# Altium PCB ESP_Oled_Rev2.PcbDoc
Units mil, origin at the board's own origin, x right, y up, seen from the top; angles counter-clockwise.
Board outline 1333.02 x 881.03 mil, 2 copper layers (Top Layer, Bottom Layer); 26 components, 22 nets, 116 pads, 21 vias.
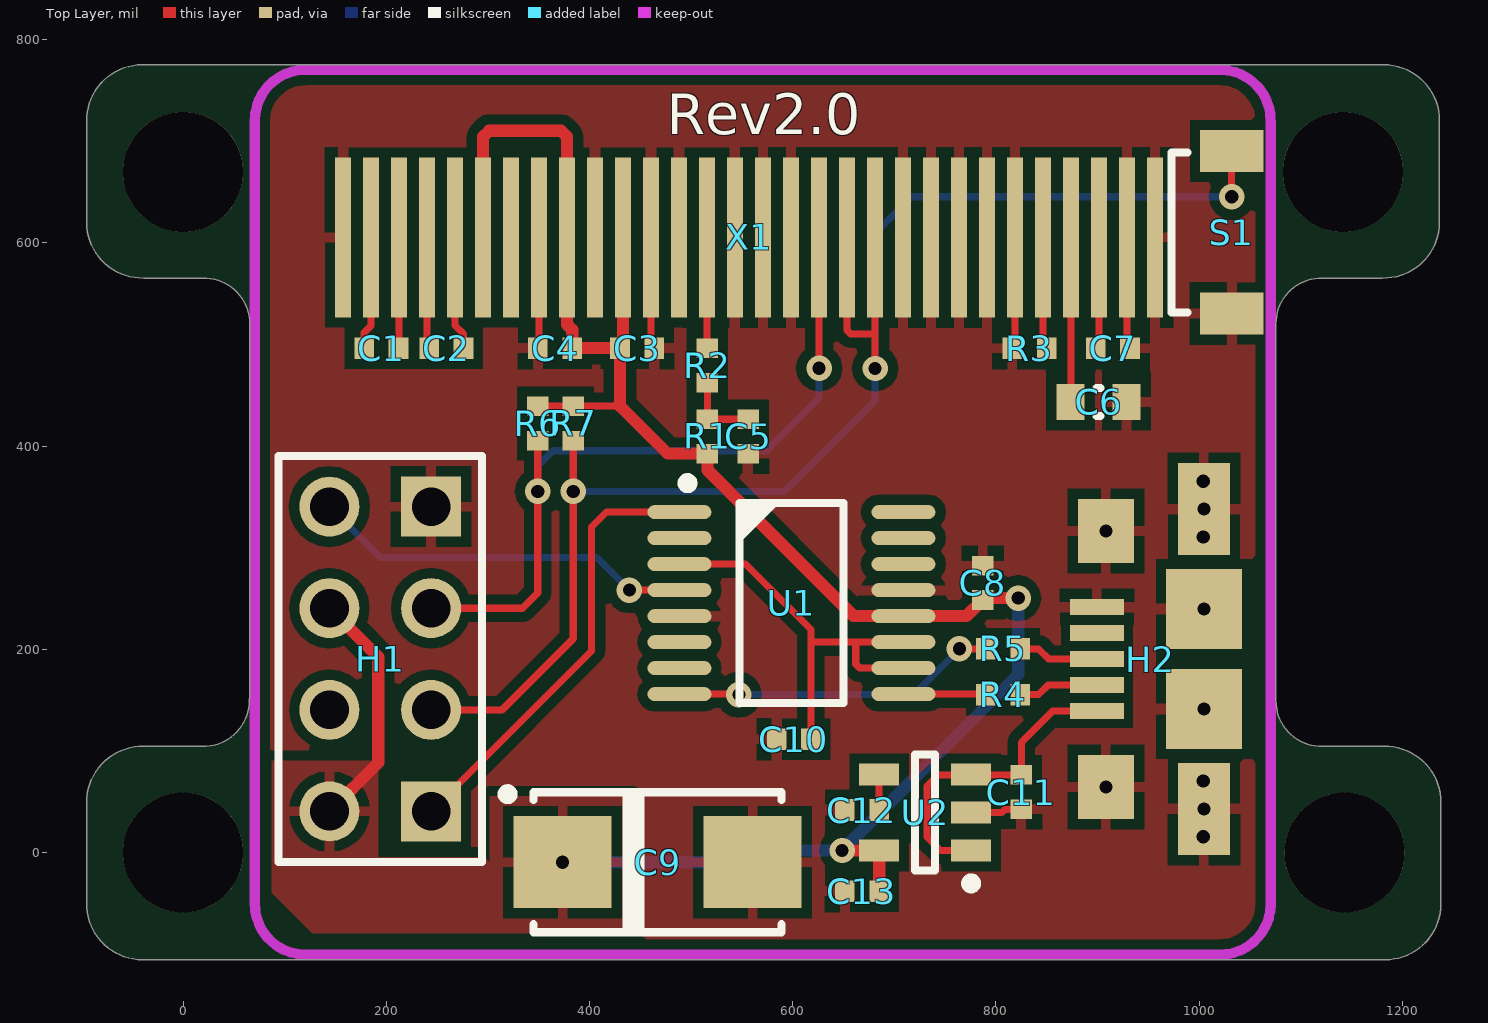
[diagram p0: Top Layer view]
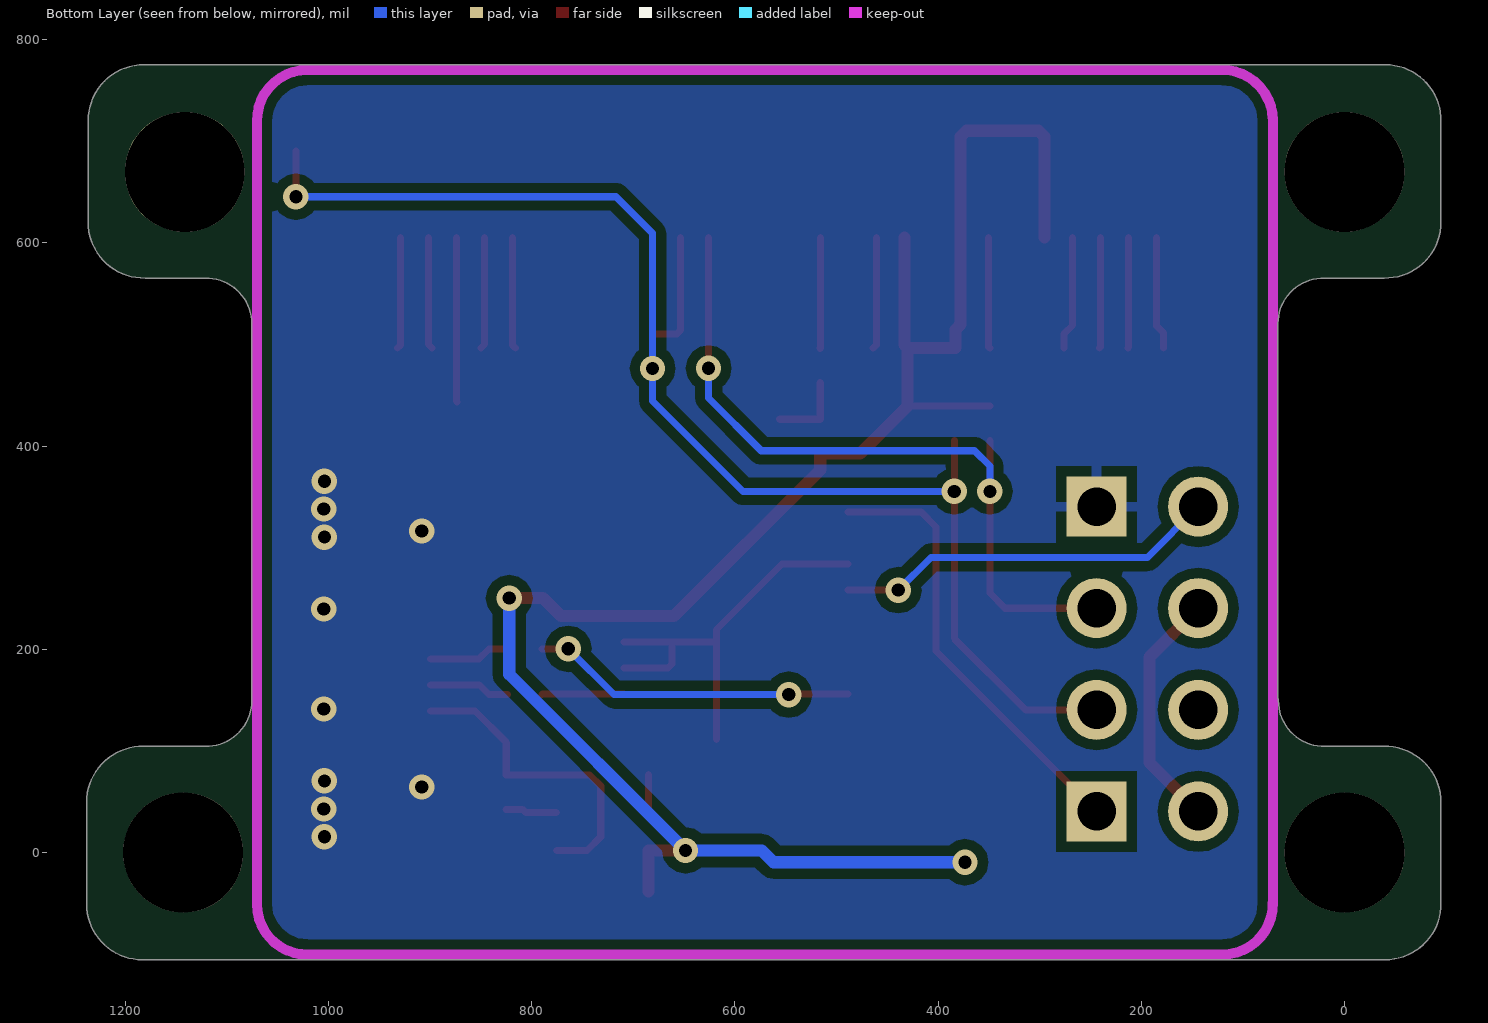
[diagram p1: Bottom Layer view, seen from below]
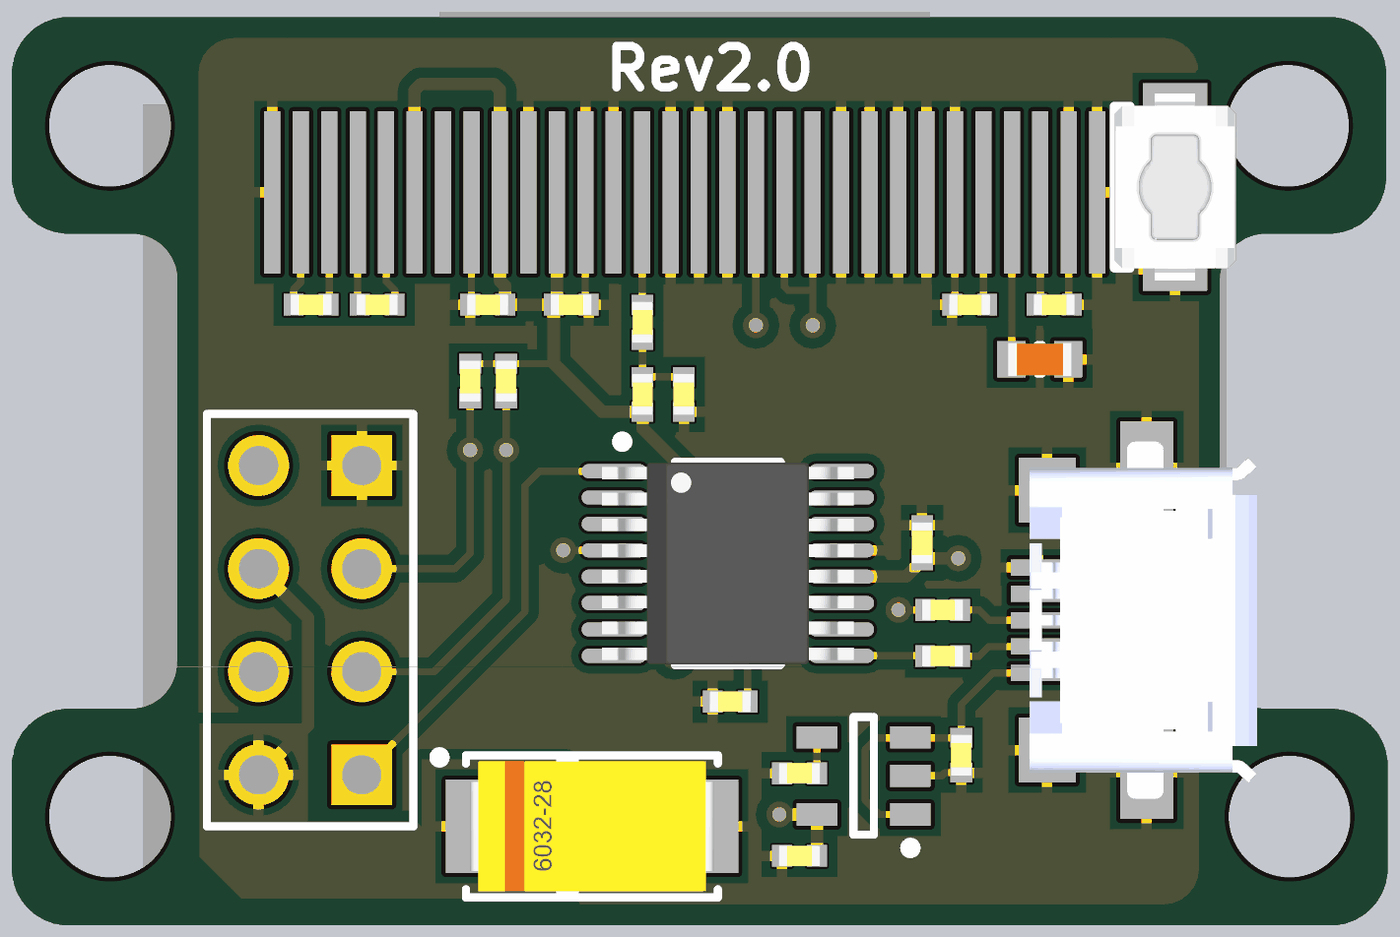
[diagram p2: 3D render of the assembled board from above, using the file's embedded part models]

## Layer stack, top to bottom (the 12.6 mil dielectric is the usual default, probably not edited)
Top Solder: solder mask 0.4, Solder Resist, Dk 3.5
Top Layer: signal copper 1.4
Dielectric 1: dielectric 12.6, FR-4, Dk 4.8
Bottom Layer: signal copper 1.4
Bottom Solder: solder mask 0.4, Solder Resist, Dk 3.5

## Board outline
-95.01,-49.43 ccw(c-40,-50.48) -40,-105.49 ccw(c-40,-100.48) -40,-105.49 120.02,-105.49 ccw(c120.5,-100.5) 120.5,-105.52 1019.5,-105.52 ccw(c1019.5,-100.5) 1020.11,-105.48 1182.56,-105.48 ccw(c1183,-100.48) 1183,-105.5 ccw(c1183,-50.48) 1238.01,-50.48 ccw(c1183,-50.48) 1238,-49.43 ccw(c1183,-50.48) 1238,-49.38 1238,-49.48 1238,49.52 ccw(c1182.99,49.52) 1181.94,104.52 ccw(c1182.99,49.52) 1181.89,104.52 1181.99,104.52 1121.5,104.52 ccw(c1121.5,99.51) 1121.37,104.52 cw(c1120.5,149.5) 1075.51,149.5 1075.51,520.5 cw(c1120.5,520.5) 1121.37,565.48 cw(c1120.5,520.5) 1121.4,565.48 1121.37,565.48 ccw(c1121.5,570.49) 1121.5,565.47 1180.44,565.47 ccw(c1181.49,620.48) 1236.5,620.48 1236.5,719.43 ccw(c1181.5,720.48) 1236.51,720.48 ccw(c1181.5,720.48) 1181.5,775.49 ccw(c1181.5,720.48) 1181.5,775.49 -40,775.52 ccw(c-40,770.5) -40.5,775.49 ccw(c-40,720.48) -95.01,719.43 ccw(c-40,720.48) -95,719.38 -95.01,719.48 -95.01,620.48 ccw(c-39.99,620.48) -38.94,565.47 ccw(c-39.99,620.48) -38.89,565.48 -38.99,565.47 19.5,565.47 ccw(c19.5,570.49) 19.63,565.48 ccw(c20.5,520.5) 19.6,565.48 19.63,565.48 cw(c20.5,520.5) 65.48,520.5 65.48,152.5 ccw(c70.5,152.5) 65.54,151.79 ccw(c70,149.5) 64.98,149.5 cw(c20,149.5) 19.15,104.52 cw(c20,149.5) 19.1,104.52 19.15,104.52 ccw(c19,99.51) 19,104.53 -38.94,104.53 cw(c-39.99,49.52) -38.89,104.52 -38.94,104.53 ccw(c-39.99,49.52) -95.01,49.52 -95.01,-49.43 cw(c-40,-50.48)

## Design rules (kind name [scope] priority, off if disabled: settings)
Clearance Clearance_H2 [InComponent('H2')] p1: gap=9
Clearance [All] p2: gap=10
MinimumSolderMaskSliver [All] p1: minsoldermaskwidth=3
PolygonConnect PolygonConnect_VIA [(IsVia)] p1: connectstyle=Direct reliefconductorwidth=10 reliefentries=4 polygonreliefangle="90 Angle" airgapwidth=10
PolygonConnect [All] p2: connectstyle=Relief reliefconductorwidth=10 reliefentries=4 polygonreliefangle="90 Angle" airgapwidth=10
RoutingVias [All] p1: holewidth=25 width=13 viastyle="Through Hole" minholewidth=25 minwidth=13 maxholewidth=30 maxwidth=20
SilkToSilkClearance [All] p1: silktosilkclearance=3
SilkToSolderMaskClearance [IsPad] p1: minsilkscreentomaskgap=4 clearancetoexposedcopper=TRUE
SolderMaskExpansion [All] p1: expansion=4
Width [All] p1: maxlimit=12 minlimit=7 preferedwidth=7
27 further rules are at their usual default settings.

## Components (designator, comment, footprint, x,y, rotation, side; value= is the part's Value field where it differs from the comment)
C1 "1uF" CHIP_1005L 195,496.5 r180 top
C2 "1uF" CHIP_1005L 259,496.5 r180 top
C3 "1uF" CHIP_1005L 446.93,496.5 r180 top
C4 "1uF" CHIP_1005L 366,496.5 r0 top
C5 "1uF" CHIP_1005L 556,409.57 r90 top
C6 "4.7uF" CAPC1608X09L 901,443.5 r180 top
C7 "2.2uF" CHIP_1005L 915,496.5 r180 top
C8 "2.2uF" CHIP_1005L 787,265.5 r90 top
C9 "220uF" CAPMP6032X260N_POL 467,-9.5 r0 top
C10 "0.1uF" CHIP_1005L 601,111.5 r180 top
C11 "1uF" CHIP_1005L 825,59.5 r270 top
C12 "10nF" CHIP_1005L 668.12,41.88 r180 top
C13 "2.2uF" CHIP_1005L 668.12,-38.12 r180 top
H1 "" ESP8266 194,190.5 r270 top
H2 "Micro USB" 1981584-1 952,190.5 r90 top
R1 "10K" CHIP_1005L 516,409.57 r270 top
R2 "10K" CHIP_1005L 516,479.43 r90 top
R3 "390K" CHIP_1005L 833,496.5 r0 top
R4 "27R" CHIP_1005L 806.8,155.5 r180 top
R5 "27R" CHIP_1005L 806.8,200.5 r180 top
R6 "4.7K" CHIP_1005L 349,422.43 r270 top
R7 "4.7K" CHIP_1005L 384,422.43 r270 top
S1 "PPushButton" TL1015AF160QG 1032,610.5 r90 top
U1 "" SOP65P602X173-16N 598.73,245.5 r0 top
U2 "CAT6219-330TDGT3" ONSC-SOT23-5_L 730.32,39.48 r180 top
X1 "OLED_GLASS" "OLED_GLASS 0.96 INCH" 557,605.5 r0 bottom

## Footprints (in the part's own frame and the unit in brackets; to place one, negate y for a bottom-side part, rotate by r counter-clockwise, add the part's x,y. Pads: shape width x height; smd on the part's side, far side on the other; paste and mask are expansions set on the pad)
1981584-1 [mm] "CONN RCPT MICRO USB TYPE AB"
  rect 0.4x1.35 smd: 1(-1.3,1.338) 2(-0.65,1.338) 3(0,1.338) 4(0.65,1.338) 5(1.3,1.338)
  rect 2.3x1.3 smd: ""(-3.75,-1.337) ""(3.75,-1.337)
  rect 1.6x1.4 smd: ""(-3.2,1.113) ""(3.2,1.113)
  rect 2x1.9 smd: ""(-1.25,-1.337) ""(1.25,-1.337)
  body extent -4.4,-4.05 4.4,1.55, height 2.75
CAPC1608X09L [mm] "Chip Capacitor, 2-Leads, Body 1.6x0.8mm, IPC High Density (0603 dense)"
  rect 0.7x0.9 smd: 1(-0.7,0) 2(0.7,0)
  silkscreen extent -0.05,-0.35 0.05,0.35, body extent -0.89,-0.48 0.88,0.48, height 1.03
CAPMP6032X260N_POL [mm] "Molded Capacitor, 2-Leads, Body 6.0x3.3mm, IPC Medium Density(C6032 POL)"
  rect 2.45x2.3 smd: 1(-2.375,0) 2(2.375,0)
  silkscreen extent -3.88,-1.75 3.1,1.82, body extent -3,-1.6 3,1.6, height 2.59
CHIP_1005L [mm] "Chip  Body 1.0x0.5mm, IPC Least Density (0402)  0.4mm"
  rect 0.49x0.54 smd mask+0.051: 1(-0.43,0) 2(0.43,0)
  body extent -0.51,-0.26 0.51,0.26, height 0.36
ESP8266 [mm]
  round 1.5 hole 0.965: 1(-3.81,-1.27) 3(-1.27,-1.27) 4(-1.27,1.27) 5(1.27,-1.27) 6(1.27,1.27) 7(3.81,-1.27)
  rect 1.5x1.5 hole 0.965: 2(-3.81,1.27) 8(3.81,1.27)
  silkscreen extent -5.08,-2.54 5.08,2.54
"OLED_GLASS 0.96 INCH" [mm] "OLED_GLASS 0.96 INCH"
  rect 0.4x4 smd far side: 1(-10.15,0) 2(-9.45,0) 3(-8.75,0) 4(-8.05,0) 5(-7.35,0) 6(-6.65,0) 7(-5.95,0) 8(-5.25,0) 9(-4.55,0) 10(-3.85,0) 11(-3.15,0) 12(-2.45,0) 13(-1.75,0) 14(-1.05,0) 15(-0.35,0) 16(0.35,0) 17(1.05,0) 18(1.75,0) 19(2.45,0) 20(3.15,0) 21(3.85,0) 22(4.55,0) 23(5.25,0) 24(5.95,0) 25(6.65,0) 26(7.35,0) 27(8.05,0) 28(8.75,0) 29(9.45,0) 30(10.15,0)
  body extent -13.33,-4.44 13.34,17.15, height 2.31
ONSC-SOT23-5_L [mm] "SOT23, 5-Leads, Body 2.90x1.6mm, Pitch 0.95mm, IPC High Density"
  rect 1x0.55 smd: 1(-1.15,0.95) 2(-1.15,0) 3(-1.15,-0.95) 4(1.15,-0.95) 5(1.15,0.95)
  silkscreen extent -1.28,-1.45 0.25,1.9, body extent -0.8,-1.45 0.8,1.45, height 1
SOP65P602X173-16N [mm] "SOP, 16-Leads, Body 5.0x4.0mm (max), Pitch 0.65mm, IPC Medium Density"
  oval 1.6x0.35 smd mask+0.076: 1(-2.8,2.275) 2(-2.8,1.625) 3(-2.8,0.975) 4(-2.8,0.325) 5(-2.8,-0.325) 6(-2.8,-0.975) 7(-2.8,-1.625) 8(-2.8,-2.275) 9(2.8,-2.275) 10(2.8,-1.625) 11(2.8,-0.975) 12(2.8,-0.325) 13(2.8,0.325) 14(2.8,0.975) 15(2.8,1.625) 16(2.8,2.275)
  silkscreen extent -2.72,-2.5 1.3,3.12, body extent -3.1,-2.49 3.1,2.49, height 1.78
TL1015AF160QG [mm] "SWITCH TACTILE SPST-NO 0.05A 12V"
  rect 1.05x1.59 smd: 1(-2.032,0) 2(2.032,0)
  silkscreen extent -2,1.1 2,1.5, body extent -2.3,-1.5 2.3,1.5, height 2

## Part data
C1 C2 C3 C4 C10 C11: library part CAP_0603, "CAP CER 0.1UF 0402"
C5: library part CAP_0603, "CAP 1uF 0402"
C6: library part CAP_0603, "CAP 4.7uF 0603"
C7: library part CAP_0603, "CAP 0603"
C8: library part CAP_0805, "CAP CER 2.2uF 0402"
C9: library part CAP_TANT_6032, "CAP TANT 220UF 6.3V 10% 2312"
C12: library part CAP_0603, "CAP CER 10nF 0402"
C13: library part CAP_0805, "CAP CER 2.2UF 0402"
H1: library part ESP8266, "ESP8266"
H2: library part 1981584-1, "CONN RCPT MICRO USB TYPE AB"
R1 R2: library part RES_0603, "RES SMD 10K 0402"
R3: library part RES_0603, "RES SMD 390K 0402"
R4 R5: library part RES_0603, "RES SMD 27 OHM 0402"
R6 R7: library part RES_0402, "RES 0402"
S1: library part DX_MINI_TACT_SWITCH, "DX_SWITCH TACTILE"
U1: library part FT230XS-R, "IC USB SERIAL BASIC UART 16SSOP"
U2: library part CMP-0273-00001-2, "Fixed Low Drop Positive Voltage Regulator, 3.3V, 5-Pin TSOT-23, Tape and Reel"

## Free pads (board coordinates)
  round 118 hole 118 unplated: ""(0,0) ""(0,670) ""(1141.5,670) ""(1143,0)

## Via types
v1: diameter 25, hole 13, Top Layer to Bottom Layer, tented both sides, 20 vias
v2: diameter 25, hole 13, Top Layer to Bottom Layer, tented bottom, 1 vias

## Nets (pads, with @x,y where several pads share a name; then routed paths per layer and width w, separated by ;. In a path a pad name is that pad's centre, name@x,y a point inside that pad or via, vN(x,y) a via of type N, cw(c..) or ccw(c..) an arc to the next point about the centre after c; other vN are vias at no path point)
GND: C3.1 C4.1 C5.1 C6.1 C7.1 C8.2 C9.2 C10.2 C11.2 C12.2 C13.2 H1.2 H2. H2.5 R3.1 S1.1 U1.5 U1.13 U2.2 X1.1 X1.8 X1.10 X1.12 X1.13 X1.15 X1.16 X1.17 X1.21 X1.22 X1.23 X1.24 X1.25 X1.29 X1.30 | length 490.9
  Top Layer w7: C4.1 350.31,497.74 X1.8 ; X1.12 460.54,499.81 C3.1 ; U2.2 805.98,39.48 809.07,42.57 C11.2 ; R3.1 818.81,499.24 X1.25 ; X1.29 929.05,499.38 C7.1
  other v1: 1004,15.5 1004.66,42.86 908.2,64.52 1004,70.5 1004.66,141.29 1004.66,239.71 1004,310.5 908.2,316.48 1004.66,338.14 1004,365.5
NetC1_1: C1.1 X1.3 | length 109.2
  Top Layer w7: X1.3 212.51,496.92 C1.1@212.93,496.5
NetC1_2: C1.2 X1.2 | length 111.9
  Top Layer w7: C1.2 178.07,511.57 184.95,518.45 X1.2
NetC2_1: C2.1 X1.5 | length 112.4
  Top Layer w7: X1.5 267.63,518.87 275.93,510.57 C2.1
NetC2_2: C2.2 X1.4 | length 109.4
  Top Layer w7: X1.4 240.07,497.5 C2.2@241.07,496.5
NetC5_2: C5.2 R1.1 R2.1 | length 76
  Top Layer w7: R2.1 R1.1 C5.2
NetC6_2: C6.2 X1.27 | length 162.2
  Top Layer w7: C6.2 873.93,443.99 X1.27
NetC7_2: C7.2 X1.28 | length 110.4
  Top Layer w7: C7.2 901.49,499.92 X1.28
NetC10_1: C10.1 U1.3 U1.10 U1.11 | length 426.1
  Top Layer w7: U1.3 553.61,283.89 617.93,219.57 617.93,205.5 ; C10.1 617.93,205.5 ; U1.10 665.98,181.52 662,185.5 662,207.11 ; U1.11 662,207.11 ; 617.93,205.5 619.54,207.11 662,207.11
NetC12_1: C12.1 U2.4 | length 35
  Top Layer w7: C12.1 U2.4
NetH1_1: H1.1 U1.4 | length 378.5
  Top Layer w7: v1(439.2,258.3) U1.4
  Bottom Layer w7: H1.1 194,290.5 407,290.5 v1(439.2,258.3)
NetH1_8: H1.8 U1.1 | length 438
  Top Layer w7: H1.8 402,198.5 402,320.5 416.57,335.07 U1.1
NetH2_2: H2.2 R4.1 | length 79.5
  Top Layer w7: R4.1 842,155.5 851.41,164.91 H2.2
NetH2_3: H2.3 R5.1 | length 79.8
  Top Layer w7: R5.1 842,200.5 852,190.5 H2.3
NetR2_2: R2.2 X1.14 | length 109.3
  Top Layer w7: X1.14 515.66,496.7 R2.2
NetR3_2: R3.2 X1.26 | length 110.5
  Top Layer w7: X1.26 846.37,500.06 R3.2
NetR4_2: R4.2 U1.9 | length 81.1
  Top Layer w7: U1.9 789.44,155.93 R4.2
NetR5_2: R5.2 U1.8 | length 321.6
  Top Layer w7: U1.8 v1@546.57,155.93 ; v1(764,200.5) R5.2
  Bottom Layer w7: v1(547,155.5) 719,155.5 v1(764,200.5) v1@762,200.5
SCL: H1.4 R6.2 X1.18 | length 748.9
  Top Layer w7: H1.4 334,240.5 349,255.5 v1(349,355.5) R6.2 ; v1(625.9,476.6) X1.18
  Bottom Layer w7: v1(349,355.5) 349,380.5 364,395.5 574,395.5 625.9,447.4 v1(625.9,476.6)
SDA: H1.6 R7.2 S1.2 X1.19 X1.20 | length 1523.3
  Top Layer w7: H1.6 314,140.5 384,210.5 v1(384,355.5) R7.2 ; X1.19 653.46,514.04 657,510.5 681.02,510.5 ; v1(681.02,476.48) 681.02,510.5 ; X1.20 681.02,510.5 ; v1(1032,645.5) S1.2
  Bottom Layer w7: v1(384,355.5) 592,355.5 681.02,444.52 v1(681.02,476.48) 681.02,609.52 717,645.5 v1(1032,645.5)
VCC: C3.2 C4.2 C8.1 C9.1 C13.1 H1.3 H1.7 R1.2 R6.1 R7.1 U1.12 U2.5 X1.6 X1.9 X1.11 | length 2103.3
  Top Layer w7: R6.1 R7.1 430.14,439.36
  Top Layer w12: H1.7 192,88.5 192,192.5 H1.3 ; X1.6 295.19,704.52 301.17,710.5 372,710.5 377.87,704.63 X1.9 377.87,519.63 382.93,514.57 C4.2 C3.2 ; X1.11 432.98,499.48 C3.2 ; v1(648.57,2.07) U2.5 C13.1 ; v1(822,250.5) 788.93,250.5 C8.1 771.13,232.7 U1.12 659.79,232.7 516,376.5 R1.2 476.86,392.64 430.14,439.36 430,439.5 C3.2
  Bottom Layer w12: v2(373.5,-9.5) 562,-9.5 573.57,2.07 v1(648.57,2.07) 822,175.5 v1(822,250.5)
VUSB: C11.1 H2.1 U2.1 U2.3 | length 315.9
  Top Layer w7: U2.1 745.42,2.07 732,15.5 732,65.5 742.93,76.43 C11.1 825,108.5 855.82,139.32 H2.1
pads on no net: H1.5 H2.4 U1.2 U1.6 U1.7 U1.14 U1.15 U1.16 X1.7

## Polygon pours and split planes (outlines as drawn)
VCC on Top Layer "Bottom Layer-GND" (solid, remove dead copper, pour order 0): 412,-79.5 147,-79.5 127,-79.5 92,-44.5 87,-39.5 87,90.5 190,90.5 192,88.5 192,-4.5 297,-4.5 302,-9.5 302,55.5 442,55.5 442,-79.5 407,-79.5
GND on Top Layer "Top Layer-GND" (solid, remove dead copper, pour order 2): 72,770.5 1067,770.5 1067,-99.5 72,-99.5 72,770.5
GND on Bottom Layer "Bottom Layer-GND" (solid, remove dead copper, pour order 4): 72,770.5 1072,770.5 1072,-99.5 72,-99.5 72,770.5

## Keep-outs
Keep-Out Layer:
  lines w10: 70.5,-49.5 70.5,720.5 cw(c120.5,720.5) 121.5,770.49 ; 70.51,-49.5 ccw(c120.5,-50.5) 120.5,-100.5 1019.5,-100.5 ccw(c1020.5,-50.5) 1070.5,-50.5 1070.5,719.5 ; 121.5,770.5 995.5,770.5 1020.39,770.5 cw(c1020.39,720.5) 1070.38,719.5

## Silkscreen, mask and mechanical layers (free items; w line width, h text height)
Top Overlay:
  text "Rev2.0" at 476,707 h40
Mechanical 1:
  lines w10: -40,770.48 ccw(c-40,720.48) -89.99,719.48 -89.99,620.48 ccw(c-39.99,620.48) -38.99,570.49 19.5,570.49 cw(c20.5,520.5) 70.5,520.5 70.5,152.5 ; -40,770.5 1181.5,770.48 cw(c1181.5,720.48) 1231.49,719.48 1231.49,620.48 cw(c1181.49,620.48) 1180.49,570.49 1121.5,570.49 ccw(c1120.5,520.5) 1070.5,520.5 1070.5,149.5 ccw(c1120.5,149.5) 1121.5,99.51 1153,99.51 1181.99,99.51 cw(c1182.99,49.52) 1232.99,49.52 1232.99,-49.48 cw(c1183,-50.48) 1183,-100.48 -40,-100.48 cw(c-40,-50.48) -89.99,-49.48 -89.99,49.52 cw(c-39.99,49.52) -38.99,99.51 19,99.51 ccw(c20,149.5) 70,149.5 ; 120.5,-100.5 1019.5,-100.5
